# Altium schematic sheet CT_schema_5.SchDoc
size 277 x 170 mm
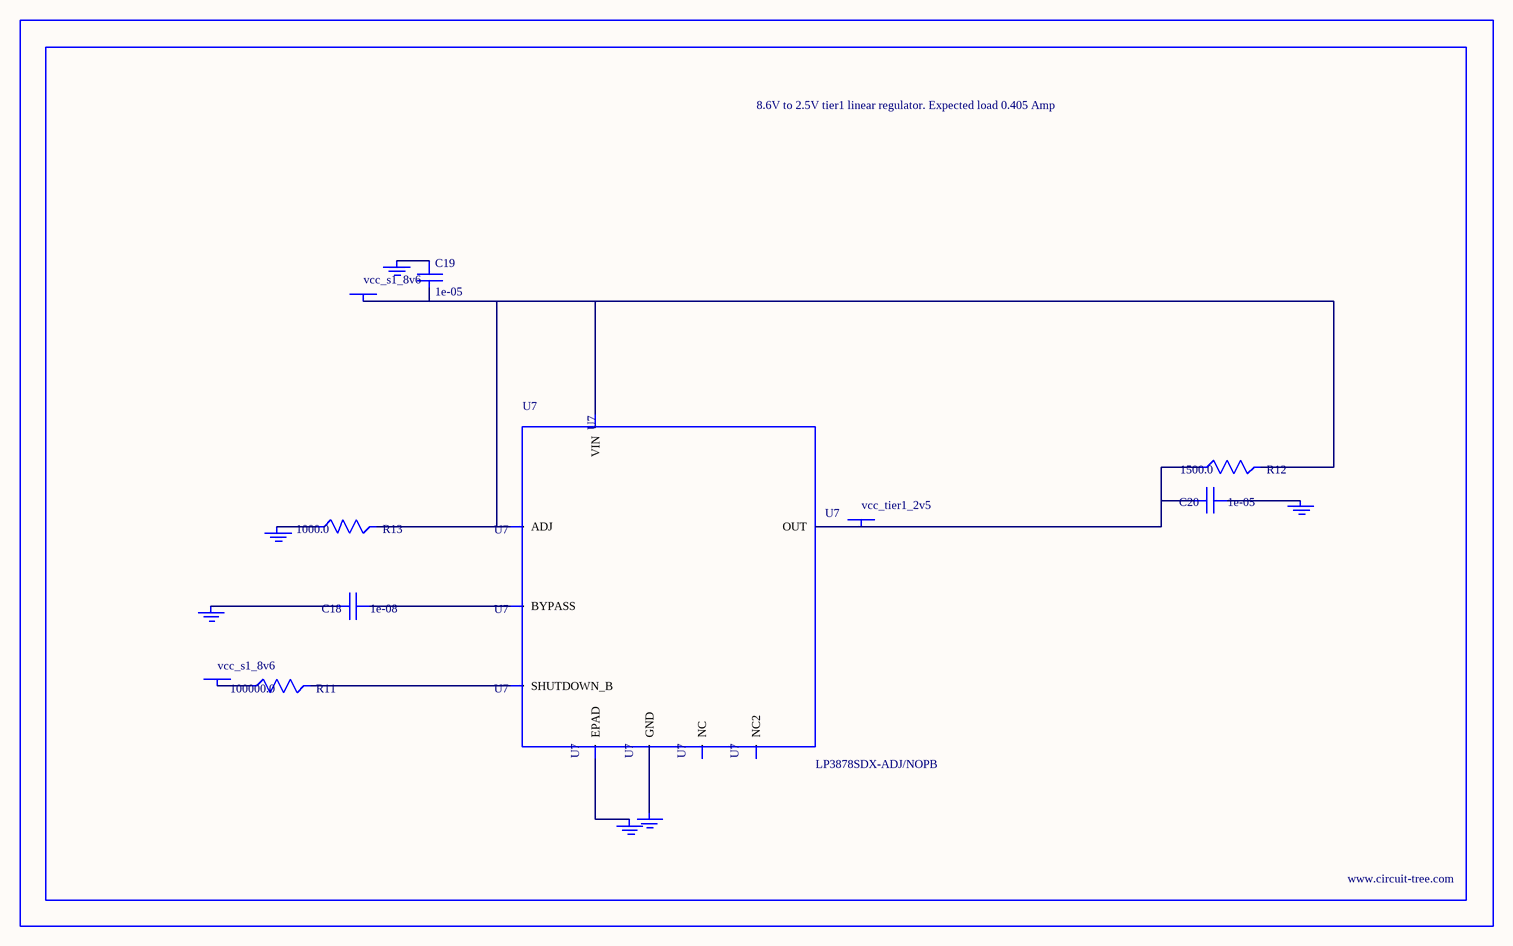
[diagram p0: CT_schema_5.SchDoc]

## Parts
BORDER4  (no value)
C18  1e-08  [C0402]
C19  1e-05  [C1206]
C20  1e-05  [C1210]
GND_INSTANCE_4_0  (no value)
GND_INSTANCE_4_1  (no value)
GND_INSTANCE_4_2  (no value)
GND_INSTANCE_4_3  (no value)
GND_INSTANCE_4_4  (no value)
GND_INSTANCE_4_5  (no value)
POWER_INSTANCE_4_0  vcc_s1_8v6
POWER_INSTANCE_4_1  vcc_s1_8v6
POWER_INSTANCE_4_2  vcc_tier1_2v5
R11  100000.0  [R0603]
R12  1500.0  [R0603]
R13  1000.0  [R0603]
U7  LP3878SDX-ADJ/NOPB  [WSON-8]

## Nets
NetC18_1: C18.1 U7.1(BYPASS)
NetC18_2: C18.2 GND_INSTANCE_4_0.0(GND)
NetC19_1: C19.1 GND_INSTANCE_4_1.0(GND)
NetC19_2: C19.2 POWER_INSTANCE_4_0.0(PWR) R12.2 R13.2 U7.4(VIN) U7.6(ADJ)
NetC20_1: C20.1 GND_INSTANCE_4_2.0(GND)
NetC20_2: C20.2 POWER_INSTANCE_4_2.0(PWR) R12.1 U7.5(OUT)
NetGND_INSTANCE_4_3_0: GND_INSTANCE_4_3.0(GND) R13.1
NetGND_INSTANCE_4_4_0: GND_INSTANCE_4_4.0(GND) U7.PAD(EPAD)
NetGND_INSTANCE_4_5_0: GND_INSTANCE_4_5.0(GND) U7.3(GND)
NetPOWER_INSTANCE_4_1_0: POWER_INSTANCE_4_1.0(PWR) R11.1
NetR11_2: R11.2 U7.8(SHUTDOWN_B)

Not connected (* = marked no-connect by the designer): U7 2(NC) 7(NC2)

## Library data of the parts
BORDER4 = BORDER_PAGE4
C18 = C0402C103K3RAC
C19 = C1206C106K3RACTU
C20 = GRM32DR61E106MA12L
GND_INSTANCE_4_0-GND_INSTANCE_4_5 = GND
POWER_INSTANCE_4_0-POWER_INSTANCE_4_2 = PWR
R11 = RC0603JR-07100KL
R12 = RC0603JR-071K5L
R13 = RC0603JR-071KL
